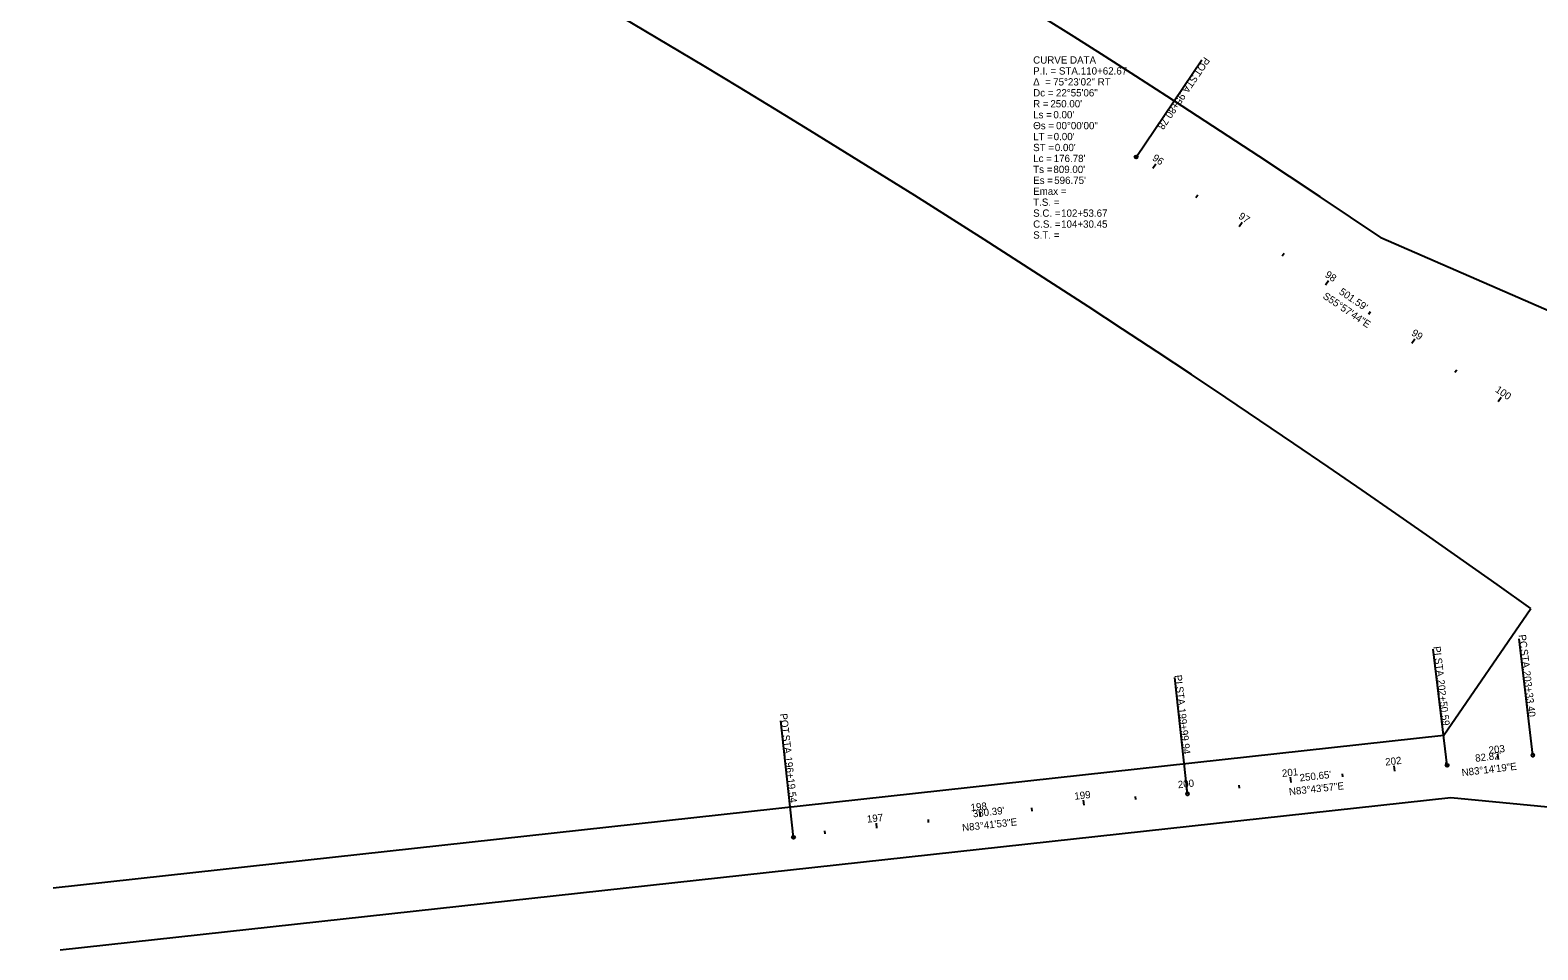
# Model space of a CAD drawing. Extents: x 1598538 to 1602183, y 285823 to 288192.
# Drawn here: x 1599295 to 1600742, y 286426 to 287309 of the extents above; entities that cross this region are included whole.
import ezdxf

# ---------------------------------------------------------------- set-up
doc = ezdxf.new("R2010")
doc.units = 0
for name, color, linetype in [('CM_Corridor_Conceptual', 7, 'Continuous'), ('CM_Corridor_Range_Conceptual', 7, 'Continuous'), ('MD_P_ACSC_B', 7, 'Continuous'), ('MD_P_ACSC_T', 7, 'Continuous'), ('MD_P_AGB_B', 7, 'Continuous'), ('PV_P_Curb', 7, 'Continuous'), ('PV_P_EOP', 7, 'Continuous')]:
    doc.layers.add(name, color=color, linetype=linetype)

msp = doc.modelspace()

# ---------------------------------------------------------------- linework, layer by layer
at = {"layer": 'MD_P_ACSC_B'}
for p, q in [((1600591.7, 287110.1), (1601244.3, 286825.5)), ((1599317.5, 286486), (1600652.1, 286632.3)), ((1599324.2, 286426.4), (1600658.7, 286572.6))]:
    msp.add_line(p, q, dxfattribs=at)
at = {"layer": 'MD_P_ACSC_T'}
for p, q in [((1600652.1, 286632.3), (1600735.5, 286754.1)), ((1600658.7, 286572.6), (1601019.6, 286537.8))]:
    msp.add_line(p, q, dxfattribs=at)
for radius, start in [(12342.7, 55.99792), (12132.2, 54.49472)]:
    msp.add_arc((1593689.4, 276877.8), radius, start, 66.44291, dxfattribs=at)
at = {"layer": 'MD_P_AGB_B'}
for p, q in [((1600372.8, 287176.6), (1600375.6, 287180.7)), ((1600414.2, 287148.6), (1600415.9, 287151.1)), ((1600455.7, 287120.6), (1600458.5, 287124.7)), ((1600497.1, 287092.6), (1600498.8, 287095.1)), ((1600538.5, 287064.6), (1600541.3, 287068.8)), ((1600580, 287036.6), (1600581.6, 287039.1)), ((1600621.4, 287008.6), (1600624.2, 287012.8)), ((1600662.8, 286980.7), (1600664.5, 286983.1)), ((1600704.3, 286952.7), (1600707.1, 286956.8)), ((1600654.7, 286603.4), (1600654.4, 286606.3)), ((1600704.4, 286609.2), (1600703.8, 286614.2)), ((1600505.6, 286587), (1600505, 286592)), ((1600555.3, 286592.4), (1600555, 286595.4)), ((1600605, 286597.9), (1600604.5, 286602.9)), ((1600406.2, 286576.1), (1600405.6, 286581)), ((1600455.9, 286581.5), (1600455.6, 286584.5)), ((1600257.1, 286559.6), (1600256.8, 286562.6)), ((1600306.8, 286565.1), (1600306.2, 286570.1)), ((1600356.5, 286570.6), (1600356.2, 286573.6)), ((1600108, 286543.1), (1600107.5, 286548.1)), ((1600157.7, 286548.6), (1600157.4, 286551.6)), ((1600207.4, 286554.1), (1600206.9, 286559.1)), ((1600058.3, 286537.7), (1600058, 286540.6))]:
    msp.add_line(p, q, dxfattribs=at)
at = {"layer": 'PV_P_Curb'}
for p, q in [((1600356.9, 287187.3), (1600419.8, 287280.5)), ((1600737.5, 286613.2), (1600724.3, 286724.9)), ((1600655.3, 286603.4), (1600642, 286715.1)), ((1600406.1, 286576.1), (1600393.8, 286687.9)), ((1600028, 286534.3), (1600015.7, 286646.1))]:
    msp.add_line(p, q, dxfattribs=at)
for centre in [(1600356.9, 287187.3), (1600655.3, 286603.4), (1600737.5, 286613.2), (1600406.1, 286576.1), (1600028, 286534.3)]:
    msp.add_circle(centre, 1.5, dxfattribs=at)

# ---------------------------------------------------------------- texts
at = {"layer": 'CM_Corridor_Conceptual'}
for s, p in [('CURVE DATA', (1600258, 287277)), ('P.I. = STA. ', (1600258, 287266.5)), ('110+62.67', (1600303.7, 287266.5)), ('Δ  = ', (1600258, 287256)), ('75°23\'02" RT', (1600277.2, 287256)), ('Dc = ', (1600258, 287245.5)), ('R = ', (1600258, 287235)), ("250.00'", (1600274.5, 287235)), ('22°55\'06"', (1600279.9, 287245.5)), ('Ls = ', (1600258, 287224.5)), ("0.00'", (1600277.4, 287224.5)), ('Θs = ', (1600258, 287214)), ('00°00\'00"', (1600280, 287214)), ('ST = ', (1600258, 287193)), ('LT = ', (1600258, 287203.5)), ("0.00'", (1600277.7, 287203.5)), ("0.00'", (1600278.8, 287193)), ('Lc = ', (1600258, 287182.5)), ("176.78'", (1600277.7, 287182.5)), ('Ts = ', (1600258, 287172)), ('Es = ', (1600258, 287161.5)), ("809.00'", (1600277.4, 287172)), ("596.75'", (1600278.2, 287161.5)), ('Emax = ', (1600258, 287151)), ('T.S. = ', (1600258, 287140.5)), ('S.C. = ', (1600258, 287130)), ('C.S. = ', (1600258, 287119.5)), ('102+53.67', (1600284.8, 287130)), ('104+30.45', (1600284.8, 287119.5)), ('S.T. = ', (1600258, 287109))]:
    msp.add_text(s, height=7, dxfattribs=at).set_placement(p)
at = {"layer": 'CM_Corridor_Range_Conceptual'}
for s, rotation, p in [("501.59'", 325.9623, (1600550.9, 287056.4)), ("82.82'", 6.7614, (1600682.6, 286606.8)), ("250.65'", 6.2675, (1600514.1, 286588)), ("380.39'", 6.3018, (1600200.5, 286553.5))]:
    msp.add_text(s, height=7, rotation=rotation, dxfattribs=at).set_placement(p)
at = {"layer": 'MD_P_AGB_B'}
for s, rotation, p in [('96', 325.9623, (1600371.7, 287184.9)), ('97', 325.9623, (1600454.4, 287129)), ('98', 325.9623, (1600537.4, 287072.9)), ('99', 325.9623, (1600620.3, 287016.9)), ('100', 325.9623, (1600700.8, 286962.5)), ('203', 6.7614, (1600695.5, 286614.5)), ('202', 6.2675, (1600596.2, 286603.2)), ('200', 6.2675, (1600397.2, 286581.4)), ('201', 6.2675, (1600497.1, 286592.3)), ('199', 6.3018, (1600297.9, 286570.4)), ('198', 6.3018, (1600198.4, 286559.4)), ('197', 6.3018, (1600098.8, 286548.4))]:
    msp.add_text(s, height=7, rotation=rotation, dxfattribs=at).set_placement(p)
at = {"layer": 'PV_P_Curb'}
for s, rotation, p in [('POT', 235.9623, (1600422.3, 287283.9)), (' STA. ', 235.9623, (1600412.2, 287269)), ('95+80.78', 235.9623, (1600399, 287249.4)), ('PC', 276.7614, (1600723.9, 286728.6)), ('PI', 276.7614, (1600641.9, 286717.3)), (' STA. ', 276.7614, (1600642.9, 286708.9)), (' STA. ', 276.7614, (1600725.3, 286717.2)), ('203+33.40', 276.7614, (1600728.1, 286693.8)), ('PI', 276.2675, (1600393.7, 286689.9)), (' STA. ', 276.2675, (1600394.7, 286681.5)), ('202+50.59', 276.7614, (1600645.7, 286685.4)), ('POT', 276.3018, (1600015, 286652.9)), ('199+99.94', 276.2675, (1600397.2, 286658)), (' STA. ', 276.3018, (1600017, 286635)), ('196+19.54', 276.3018, (1600019.6, 286611.5))]:
    msp.add_text(s, height=7, rotation=rotation, dxfattribs=at).set_placement(p)
at = {"layer": 'PV_P_EOP'}
for s, rotation, p in [('S55°57\'44"E', 325.9623, (1600535.3, 287052.3)), ('N83°14\'19"E', 6.7614, (1600669.6, 286593)), ('N83°43\'57"E', 6.2675, (1600503.8, 286574.7)), ('N83°41\'53"E', 6.3018, (1600190.2, 286540.1))]:
    msp.add_text(s, height=7, rotation=rotation, dxfattribs=at).set_placement(p)

doc.saveas('drawing.dxf')
